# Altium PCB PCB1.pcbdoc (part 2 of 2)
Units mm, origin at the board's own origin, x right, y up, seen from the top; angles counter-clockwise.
Board outline 181.85 x 97.7 mm, 4 copper layers (Top Layer, GND, VCC, Bottom Layer); 121 components, 105 nets, 379 pads, 511 vias.
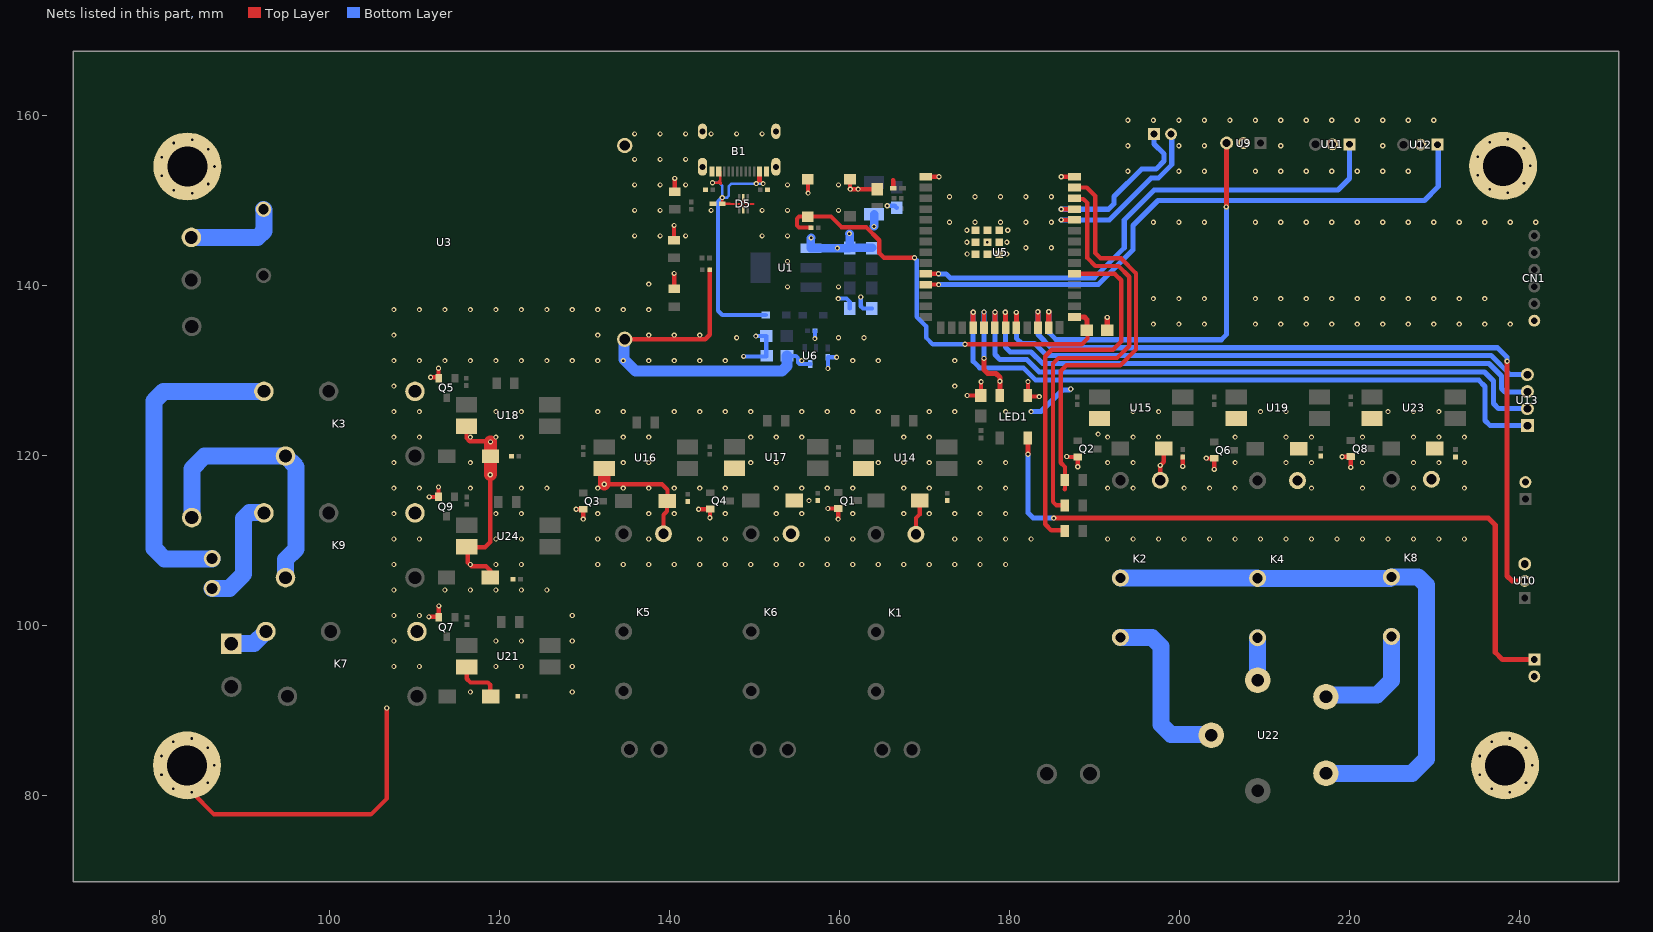
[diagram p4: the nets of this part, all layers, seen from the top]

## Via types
v1: diameter 0.61, hole 0.304, Top Layer to Bottom Layer, 331 vias
v2: diameter 0.61, hole 0.305, Top Layer to Bottom Layer, 168 vias
v3: diameter 0.5, hole 0.3, Top Layer to Bottom Layer, 12 vias

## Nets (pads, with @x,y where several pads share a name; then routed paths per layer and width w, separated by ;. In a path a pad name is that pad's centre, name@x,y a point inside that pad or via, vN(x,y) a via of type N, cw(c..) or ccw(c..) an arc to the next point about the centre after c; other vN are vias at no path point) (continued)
EXT_5V: C7.1 D1.1 D3.1 D7.1 D8.1 D9.1 D10.1 D11.1 D12.1 D13.1 K1.4 K2.4 K3.1 K4.4 K5.4 K6.4 K7.1 K8.4 K9.1 R5.1 R11.2 R12.2 R13.2 R14.2 R19.2 R20.2 R23.2 R24.2 R27.2 U3.4 U6.3 U14.4 U15.4 U16.4 U17.4 U18.4 U19.4 U21.4 U23.4 U24.4 | length 105.8
  Top Layer w0.5: U18.4@116.104,123.454 116.104,122.064 116.484,121.683 119.253,121.683 119.278,121.658 ; U21.4@116.143,95.099 116.143,93.729 116.586,93.286 118.618,93.286 118.897,93.007 118.897,91.72 D11.1@118.967,91.65 ; U24.4@116.143,109.257 U24.4@116.188,109.212 ; D13.1@118.889,105.652 118.889,106.503 118.415,106.977 116.688,106.977 116.256,107.409 116.256,109.144 U24.4@116.188,109.212 ; v2(118.898,117.742) 118.898,109.822 118.288,109.212 U24.4@116.188,109.212 ; v2(132.328,116.626) 139.119,116.626 139.776,115.968 139.776,114.722 D7.1@139.716,114.661 139.716,113.444 139.295,113.024 K5.4@139.295,110.788 ; U3.4@134.726,133.682 144.206,133.682 144.73,134.207 R5.1@144.73,141.876 ; K1.4@169.004,110.734 169.004,112.633 169.443,113.073 169.443,114.692 D1.1@169.435,114.7 ; K2.4@197.769,117.086 197.769,118.834 v2(197.764,118.839) 198.179,119.253 D3.1@198.179,120.823 ; v2(200.411,118.717) R12.2@200.411,119.845
  Top Layer w1.5: v2(118.898,117.742) 118.928,117.773 D9.1@118.928,119.926 v2(118.928,121.608) ; v2(132.328,116.626) U16.4@132.328,118.461
  Bottom Layer w0.5: C7.1@153.842,131.719 154.858,131.719 155.116,131.462 155.116,130.962 155.316,130.762 156.584,130.762 U6.3@156.592,130.769
  Bottom Layer w0.6: v1(182.564,125.171) 183.726,125.171 186.258,127.703 187.096,127.703 v2(187.223,127.83)
  Bottom Layer w1.3: U3.4@134.726,133.682 134.666,133.622 134.666,131.312 136.016,129.962 153.266,129.962 153.842,130.538 C7.1@153.842,131.719
  other v1: 116.564,92.171 128.564,92.171 107.564,95.171 110.564,95.171 119.564,95.171 122.564,95.171 128.564,95.171 107.564,98.171 119.564,98.171 122.564,98.171 128.564,98.171 107.564,101.171 110.564,101.171 128.564,101.171 107.564,104.171 113.564,104.171 116.564,104.171 119.564,104.171 122.564,104.171 125.564,104.171 107.564,107.171 116.564,107.171 119.564,107.171 122.564,107.171 131.564,107.171 134.564,107.171 137.564,107.171 140.564,107.171 143.564,107.171 146.564,107.171 149.564,107.171 152.564,107.171 155.564,107.171 158.564,107.171 161.564,107.171 164.564,107.171 167.564,107.171 170.564,107.171 173.564,107.171 176.564,107.171 179.564,107.171 107.564,110.171 110.564,110.171 119.564,110.171 122.564,110.171 131.564,110.171 137.564,110.171 143.564,110.171 146.564,110.171 152.564,110.171 158.564,110.171 161.564,110.171 173.564,110.171 176.564,110.171 179.564,110.171 182.564,110.171 191.564,110.171 194.564,110.171 197.564,110.171 200.564,110.171 203.564,110.171 206.564,110.171 209.564,110.171 212.564,110.171 215.564,110.171 218.564,110.171 221.564,110.171 224.564,110.171 227.564,110.171 230.564,110.171 233.564,110.171 107.564,113.171 119.564,113.171 122.564,113.171 131.564,113.171 137.564,113.171 140.564,113.171 146.564,113.171 152.564,113.171 155.564,113.171 161.564,113.171 167.564,113.171 170.564,113.171 173.564,113.171 176.564,113.171 179.564,113.171 107.564,116.171 110.564,116.171 116.564,116.171 122.564,116.171 125.564,116.171 131.564,116.171 134.564,116.171 137.564,116.171 140.564,116.171 143.564,116.171 146.564,116.171 152.564,116.171 155.564,116.171 158.564,116.171 161.564,116.171 167.564,116.171 170.564,116.171 176.564,116.171 179.564,116.171 191.564,116.171 194.564,116.171 200.564,116.171 203.564,116.171 206.564,116.171 215.564,116.171 221.564,116.171 227.564,116.171 233.564,116.171 107.564,119.171 116.564,119.171 134.564,119.171 137.564,119.171 149.564,119.171 152.564,119.171 164.564,119.171 167.564,119.171 170.564,119.171 176.564,119.171 179.564,119.171 191.564,119.171 194.564,119.171 206.564,119.171 212.564,119.171 215.564,119.171 221.564,119.171 227.564,119.171 230.564,119.171 233.564,119.171 107.564,122.171 110.564,122.171 116.564,122.171 119.564,122.171 122.564,122.171 134.564,122.171 137.564,122.171 149.564,122.171 152.564,122.171 155.564,122.171 167.564,122.171 170.564,122.171 191.564,122.171 194.564,122.171 197.564,122.171 206.564,122.171 212.564,122.171 215.564,122.171 221.564,122.171 227.564,122.171 230.564,122.171 233.564,122.171 107.564,125.171 110.564,125.171 119.564,125.171 122.564,125.171 131.564,125.171 134.564,125.171 140.564,125.171 143.564,125.171 146.564,125.171 149.564,125.171 155.564,125.171 158.564,125.171 161.564,125.171 164.564,125.171 170.564,125.171 173.564,125.171 179.564,125.171 194.564,125.171 197.564,125.171 209.564,125.171 212.564,125.171 224.564,125.171 227.564,125.171 230.564,125.171 107.564,128.171 173.564,128.171 107.564,131.171 110.564,131.171 113.564,131.171 116.564,131.171 119.564,131.171 122.564,131.171 125.564,131.171 128.564,131.171 131.564,131.171 134.564,131.171 137.564,131.171 140.564,131.171 143.564,131.171 146.564,131.171 155.564,131.171 161.564,131.171 164.564,131.171 173.564,131.171 107.564,134.171 131.564,134.171 137.564,134.171 140.564,134.171 143.564,134.171 107.564,137.171 110.564,137.171 113.564,137.171 116.564,137.171 119.564,137.171 122.564,137.171 125.564,137.171 128.564,137.171 131.564,137.171 134.564,137.171 137.564,137.171 137.564,140.171
  other v2: 156.417,114.7 190.449,122.522
FAN_SW: U5.18 U13.1 | length 78.3
  Top Layer w0.6: v2(175.743,136.873) 175.743,135.029 U5.18@175.746,135.026
  Bottom Layer w0.6: v2(175.743,136.873) 175.743,131.097 176.52,130.319 181.651,130.319 183.098,128.872 235.255,128.872 235.991,128.135 235.991,124.118 236.591,123.518 U13.1@240.973,123.518
FIN: K2.2 K4.2 K8.2 U22.P | length 69.5
  Bottom Layer w2: K2.2@193.069,105.586 209.176,105.586 K4.2@209.215,105.547 224.816,105.547 K8.2@224.972,105.703 224.999,105.73 228.102,105.73 229.077,104.755 229.077,84.279 227.4,82.602 U22.P@217.259,82.602
FO1: K2.3 U22.2 | length 20.9
  Bottom Layer w2: K2.3@193.069,98.586 196.79,98.586 197.837,97.539 197.837,88.335 199.007,87.165 203.687,87.165 U22.2@203.772,87.08
FO2: K4.3 U22.3 | length 5
  Bottom Layer w2: K4.3@209.215,98.547 209.215,93.575 U22.3@209.233,93.557
FO3: K8.3 U22.4 | length 13.7
  Bottom Layer w2: U22.4@217.259,91.602 217.464,91.806 223.266,91.806 224.972,93.512 K8.3@224.972,98.703
FSR1: LED5.2 U5.39 | length 48.4
  Top Layer w0.5: 186.529,116.043 186.553,116.066 186.553,118.645 186.053,119.145 186.053,129.962 186.715,130.624 193.065,130.624 194.92,132.478 194.92,141.445 193.142,143.223 190.729,143.223 190.119,143.832 190.119,150.538 189.111,151.546 U5.39@187.671,151.546
FSR2: LED7.2 U5.38 | length 49.9
  Top Layer w0.5: LED7.2@186.529,114.135 185.552,114.135 185.141,114.546 185.141,130.827 185.801,131.488 192.684,131.488 194.107,132.91 194.107,141.038 192.837,142.308 190.119,142.308 189.179,143.248 189.179,149.725 188.697,150.208 187.739,150.208 U5.38@187.671,150.276
FSR3: LED9.2 U5.31 | length 45.1
  Top Layer w0.5: LED9.2@186.529,111.135 186.471,111.193 184.937,111.193 184.222,111.908 184.222,131.687 184.988,132.453 192.202,132.453 193.167,133.418 193.167,140.632 192.413,141.386 U5.31@187.671,141.386
GND: B1.1 B1.A1 B1.A12 B1.B1 B1.B12 C1.2 C2.2 C3.2 C4.2 C5.2 C6.2 C7.2 C8.2 C9.2 C10.2 C11.2 C12.2 C13.2 C14.2 CN1.6 D5.2 LED1.3 LED11.2 LED12.2 LED13.2 pad.42 Q1.2 Q2.2 Q3.2 Q4.2 Q5.2 Q6.2 Q7.2 Q8.2 Q9.2 R8.1 R9.1 R10.2 SW1.2 SW2.2 U1.1 U3.3 U4.2 U5.1 U5.40 U5.41 U7.2 U9.2 U10.3 U11.2 U12.2 | length 108
  Top Layer w0.2: D5.2@148.692,150.348 148.692,149.836 148.916,149.612 149.916,149.612
  Top Layer w0.5: v2(83.766,80.386) 86.386,77.767 104.851,77.767 106.731,79.646 v2(106.731,90.289) ; v2(111.682,101.011) 112.779,101.011 Q7.2@112.838,100.952 112.852,100.966 v2(112.852,102.298) ; v2(111.721,115.129) 112.78,115.129 Q9.2@112.799,115.148 112.813,115.162 v2(112.813,116.299) ; v2(111.877,129.209) 112.74,129.209 Q5.2@112.813,129.136 ; v2(112.813,130.262) Q5.2@112.813,129.136 ; Q5.2@112.838,129.111 Q5.2@112.813,129.136 ; v2(129.007,113.682) 129.828,113.682 Q3.2@129.838,113.672 129.857,113.653 v2(129.857,112.516) ; v2(140.538,147.083) 140.543,147.078 LED11.2@140.543,145.353 ; v2(140.543,141.437) 140.557,141.423 LED12.2@140.557,139.616 ; v2(140.614,152.621) 140.621,152.614 LED13.2@140.621,151.068 ; v2(143.43,113.686) 144.751,113.686 Q4.2@144.776,113.711 144.776,112.692 v2(144.756,112.672) ; SW2.2@156.286,152.494 156.312,152.469 v2(156.312,150.893) ; v2(158.64,113.764) 159.855,113.764 Q1.2@159.869,113.75 159.849,113.73 v2(159.849,112.516) ; SW1.2@161.246,152.511 161.246,151.381 v2(161.265,151.362) 161.275,151.353 v2(162.196,151.353) C6.2@164.452,151.353 ; 166.319,152.417 166.333,152.404 C11.2@166.333,151.478 ; U5.1@170.171,152.816 171.712,152.816 v2(171.716,152.812) ; v2(175.021,127.064) 176.65,127.064 C5.2@176.659,127.055 176.67,127.066 v2(176.67,128.685) ; LED1.3@182.196,127.064 182.318,126.941 v2(183.515,126.941) ; LED1.3@182.197,127.065 v2(182.197,128.702) ; v2(186.116,152.812) 187.668,152.812 U5.40@187.671,152.816 ; v2(186.76,119.887) 186.813,119.834 Q2.2@188.028,119.834 188.047,119.815 v2(188.047,118.678) ; v2(203.18,119.692) 203.213,119.659 Q6.2@204.116,119.659 ; Q6.2@204.097,119.678 Q6.2@204.116,119.659 ; v2(204.116,118.366) Q6.2@204.116,119.659 ; v2(219.171,119.848) 220.18,119.848 Q8.2@220.185,119.853 ; v2(220.185,118.6) Q8.2@220.185,119.853 ; Q8.2@220.205,119.873 Q8.2@220.185,119.853
  Top Layer w0.6: C10.2@191.522,134.764 v2(191.522,136.263)
  Bottom Layer w0.5: v2(148.716,131.662) 151.384,131.662 C7.2@151.389,131.666 ; v2(150.166,134.062) 151.384,134.062 C12.2@151.392,134.069 C7.2@151.392,131.769 ; v2(157.116,133.762) 157.125,133.771 R8.1@157.125,134.669 ; v2(158.642,130.245) C13.2@158.642,131.574 159.653,131.574 v2(159.665,131.562) ; v2(159.868,138.473) 160.833,138.473 161.229,138.076 C2.2@161.229,137.311 ; v2(162.515,138.662) 162.515,137.577 162.785,137.308 163.826,137.308 C1.2@163.829,137.311 ; v2(165.633,149.395) 166.504,149.395 C9.2@166.737,149.162
  Bottom Layer w1: v2(156.666,145.612) 156.649,145.596 U1.1@156.649,144.411 v2(159.765,144.412) ; v2(159.765,144.412) C4.2@161.166,144.412 ; C4.2@161.166,144.462 161.19,144.486 161.19,146.116 v2(161.179,146.127) ; C4.2@161.19,144.436 C3.2@163.84,144.436 ; v2(164.065,146.962) 164.087,146.983 C8.2@164.087,148.401
  other v1: 147.893,133.853 159.893,133.853 162.893,133.853 196.954,135.464 199.954,135.464 202.954,135.464 208.954,135.464 211.954,135.464 214.954,135.464 217.954,135.464 220.954,135.464 223.954,135.464 226.954,135.464 229.954,135.464 232.954,135.464 235.954,135.464 238.954,135.464 196.954,138.464 199.954,138.464 202.954,138.464 208.954,138.464 211.954,138.464 214.954,138.464 217.954,138.464 220.954,138.464 223.954,138.464 226.954,138.464 229.954,138.464 232.954,138.464 235.954,138.464 153.893,139.853 159.893,139.853 153.893,142.853 181.954,144.464 184.954,144.464 135.893,145.853 138.893,145.853 141.893,145.853 150.893,145.853 153.893,145.853 172.954,147.464 175.954,147.464 178.954,147.464 181.954,147.464 184.954,147.464 196.954,147.464 199.954,147.464 202.954,147.464 208.954,147.464 211.954,147.464 214.954,147.464 217.954,147.464 220.954,147.464 223.954,147.464 226.954,147.464 229.954,147.464 232.954,147.464 235.954,147.464 238.954,147.464 241.954,147.464 135.893,148.853 138.893,148.853 144.893,148.853 150.893,148.853 153.893,148.853 159.893,148.853 172.954,150.464 175.954,150.464 178.954,150.464 181.954,150.464 184.954,150.464 135.893,151.853 138.893,151.853 141.893,151.853 153.893,151.853 159.893,151.853 193.954,153.464 199.954,153.464 202.954,153.464 208.954,153.464 211.954,153.464 214.954,153.464 217.954,153.464 220.954,153.464 223.954,153.464 226.954,153.464 135.893,154.853 138.893,154.853 141.893,154.853 193.954,156.464 199.954,156.464 202.954,156.464 211.954,156.464 223.954,156.464 135.893,157.853 138.893,157.853 141.893,157.853 144.893,157.853 147.893,157.853 150.893,157.853 193.954,159.464 196.954,159.464 199.954,159.464 202.954,159.464 205.954,159.464 208.954,159.464 211.954,159.464 214.954,159.464 217.954,159.464 220.954,159.464 223.954,159.464 226.954,159.464 229.954,159.464
  other v2: 238.915,80.386 81.611,80.767 236.759,80.767 85.662,81.481 240.81,81.481 80.204,82.443 80.204,82.443 235.352,82.443 235.352,82.443 86.411,83.538 86.411,83.538 241.559,83.538 241.559,83.538 80.204,84.632 235.352,84.632 85.662,85.595 240.81,85.595 81.611,86.309 236.759,86.309 83.766,86.689 238.915,86.689 175.021,143.717 179.716,143.712 174.998,145.095 177.421,145.095 179.716,145.112 174.998,146.521 179.818,146.525 83.805,150.862 238.681,150.94 81.65,151.242 236.525,151.32 85.701,151.957 240.576,152.035 80.243,152.919 80.243,152.919 235.118,152.997 235.118,152.997 86.45,154.014 86.45,154.014 241.325,154.092 241.325,154.092 80.243,155.108 235.118,155.186 85.701,156.071 240.576,156.149 81.65,156.785 236.525,156.863 83.805,157.165 238.681,157.243
IO0: C10.1 R4.1 SW2.1 U5.27 | length 52.8
  Top Layer w0.5: SW2.1@156.286,148.124 159.004,148.124 160.249,146.88 163.147,146.88 164.694,145.333 164.694,143.832 165.252,143.273 v2(168.834,143.273) ; SW2.1@156.286,148.124 155.246,148.125 154.998,147.877 154.998,147.06 155.229,146.829 R4.1@156.641,146.829 ; v2(174.777,133.088) 188.519,133.088 189.205,133.774 189.205,134.682 C10.1@189.122,134.764
  Top Layer w0.6: U5.27@187.671,136.306 188.832,136.306 189.154,135.984 189.154,134.796 C10.1@189.122,134.764
  Bottom Layer w0.5: v2(168.834,143.273) 169.088,143.019 169.088,136.339 170.205,135.222 170.205,133.875 170.993,133.088 v2(174.777,133.088)
IR_RX: U5.11 U12.1 | length 71.7
  Top Layer w0.5: U5.11@170.171,140.116 v2(171.679,140.116)
  Bottom Layer w0.6: v2(171.679,140.116) 190.465,140.116 194.564,144.214 194.564,147.083 197.506,150.025 228.849,150.025 230.48,151.655 230.48,156.508 U12.1@230.4,156.588
IR_TX: U5.10 U11.1 | length 60.8
  Top Layer w0.5: U5.10@170.171,141.386 v2(171.661,141.386)
  Bottom Layer w0.6: v2(171.661,141.386) 172.55,141.386 173.025,140.911 189.992,140.911 193.523,144.442 193.523,147.718 197.053,151.249 218.669,151.249 220.026,152.606 U11.1@220.026,156.627
N: U2.2 U3.1 | length 11.5
  Bottom Layer w2: U2.2@83.718,145.671 91.522,145.671 92.298,146.447 92.298,148.91 U3.1@92.226,148.983
NO1: CN6.1 K3.3 | length 38.1
  Bottom Layer w2: CN6.1@86.175,107.87 86.141,107.836 80.559,107.836 79.35,109.045 79.35,126.44 80.469,127.559 K3.3@92.262,127.559
NO2: CN6.2 K9.3 | length 13.6
  Bottom Layer w2: CN6.2@86.175,104.37 88.208,104.37 89.866,106.027 89.866,112.594 90.556,113.284 K9.3@92.223,113.284
NO3: CN5.1 K7.3 | length 4.6
  Bottom Layer w2: CN5.1@88.437,97.856 91.07,97.856 K7.3@92.496,99.282
P: K3.4 K9.4 U25.2 | length 32.7
  Bottom Layer w2: U25.2@83.772,112.694 83.772,118.409 85.289,119.926 94.79,119.926 K3.4@94.802,119.939 96.063,118.678 96.063,109.009 94.802,107.748 K9.4@94.802,105.625
PIR: U5.24 U10.2 | length 89
  Top Layer w0.6: v2(183.363,136.923) 183.363,135.029 U5.24@183.366,135.026 ; v2(238.582,131.107) 238.582,105.834 239.179,105.237 U10.2@240.661,105.237
  Bottom Layer w0.6: v2(183.363,136.923) 183.363,134.231 184.912,132.682 237.465,132.682 238.582,131.564 v2(238.582,131.107)
RGB: LED1.4 U5.19 | length 13.1
  Top Layer w0.5: v2(177.013,136.898) 177.016,136.894 U5.19@177.016,135.026
  Top Layer w0.6: v2(177.013,131.437) 177.013,130.091 177.444,129.659 178.435,129.659 178.892,129.202 v2(178.892,128.745) 178.894,128.743 LED1.4@178.894,127.062
  Bottom Layer w0.6: v2(177.013,131.437) v2(177.013,136.898)
RGB_O: LED1.2 U7.1 | length 84.3
  Top Layer w0.6: v2(182.194,120.159) LED1.2@182.194,122.062 ; v2(185.217,112.641) 236.372,112.641 237.185,111.828 237.185,96.842 238.023,96.004 U7.1@241.792,96.004
  Bottom Layer w0.6: v2(182.194,120.159) 182.194,113.251 182.804,112.641 v2(185.217,112.641)
RS2: U5.20 U13.2 | length 73.7
  Top Layer w0.6: U5.20@178.286,135.026 178.308,135.047 v2(178.308,136.873)
  Bottom Layer w0.6: v2(178.308,136.873) 178.308,131.885 178.908,131.285 182.067,131.285 183.515,129.837 235.925,129.837 236.982,128.78 236.982,126.118 237.582,125.518 U13.2@240.973,125.518
RS3: U5.21 U13.3 | length 70.5
  Top Layer w0.6: v2(179.527,136.873) 179.527,135.055 U5.21@179.556,135.026
  Bottom Layer w0.6: v2(179.527,136.873) 179.527,132.783 180.111,132.199 182.55,132.199 183.921,130.827 236.449,130.827 237.922,129.354 237.922,127.881 238.328,127.475 240.93,127.475 U13.3@240.973,127.518
RS4: U5.22 U13.4 | length 66.8
  Top Layer w0.6: v2(180.823,136.847) 180.823,135.029 U5.22@180.826,135.026
  Bottom Layer w0.6: v2(180.823,136.847) 180.823,133.79 181.423,133.19 182.982,133.19 184.404,131.767 236.705,131.767 238.955,129.518 U13.4@240.973,129.518
RXD0: U5.36 U8.2 | length 20.9
  Top Layer w0.5: v2(186.106,147.736) U5.36@187.671,147.736
  Bottom Layer w0.6: v2(186.106,147.736) 191.762,147.736 196.672,152.646 197.521,152.646 199.111,154.236 199.111,157.757 U8.2@199.032,157.836
TMP: U5.25 U9.3 | length 48.4
  Top Layer w0.6: v2(184.633,136.923) 184.633,135.029 U5.25@184.636,135.026 ; v2(205.537,149.268) 205.573,149.304 U9.3@205.573,156.783
  Bottom Layer w0.6: v2(184.633,136.923) 184.633,134.51 185.522,133.621 204.937,133.621 205.537,134.221 v2(205.537,149.268)
TXD0: U5.37 U8.1 | length 20.2
  Top Layer w0.5: v2(186.106,148.988) 187.654,148.988 U5.37@187.671,149.006
  Bottom Layer w0.6: v2(186.106,148.988) 191.683,148.988 192.329,149.634 192.329,150.482 195.585,153.738 197.282,153.738 198.204,154.66 198.204,155.509 197.032,156.681 U8.1@197.032,157.836
VBUS: B1.A4 B1.A9 B1.B4 B1.B9 C14.1 D2.1 D5.5 | length 37.8
  Top Layer w0.2: 147.066,149.612 148.456,149.612 148.692,149.376 D5.5@148.692,148.899
  Top Layer w0.3: v2(145.066,152.112) 145.716,152.112 ; B1.A9@145.652,153.418 B1.B4@145.952,153.418 145.952,152.348 145.716,152.112 ; 146.05,152.012 146.05,152.112 145.716,152.112 ; v2(146.216,150.362) 146.216,149.617 C14.1@146.211,149.612 147.066,149.612 ; v2(150.216,152.012) 150.452,152.248 B1.B9@150.452,153.418 ; B1.A4@150.752,153.418 150.752,152.275 v2(151.016,152.012)
  Bottom Layer w0.3: v2(145.066,152.112) 145.816,152.112 146.216,151.712 v2(146.216,150.362) 146.766,150.362 146.966,150.562 146.966,151.662 147.316,152.012 v2(150.216,152.012) v2(151.016,152.012)
  Bottom Layer w0.5: v2(146.216,150.362) 145.716,149.862 145.716,137.037 146.216,136.537 D2.1@151.342,136.537
pads on no net: B1.A8 B1.B8 K3.2 K7.2 K9.2 U5.16 U5.26 U5.28 U5.29 U5.30 U5.32 U5.33 U5.34 U5.35 U20.1 U20.2 U22.1
copper on no net:
  other v3: 176.721,143.695 178.121,143.695 176.021,144.395 177.421,144.395 178.821,144.395 176.721,145.095 178.121,145.095 176.021,145.795 177.421,145.795 178.821,145.795 176.721,146.495 178.121,146.495

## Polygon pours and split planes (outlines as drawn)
GND on Top Layer (solid, remove dead copper, pour order 8): 174.553,142.976 180.249,142.976 180.249,147.359 174.553,147.359
GND on Top Layer (solid, remove dead copper, pour order 0): 244.094,88.714 244.958,87.851 244.958,76.903 234.496,76.903 233.786,77.696 233.786,87.88 234.62,88.714
GND on Top Layer (solid, remove dead copper, pour order 2): 233.481,160.672 244.678,160.672 244.678,149.293 244.018,148.633 233.782,148.633 232.918,149.496 232.918,160.109
GND on Top Layer (solid, remove dead copper, pour order 4): 145.491,133.672 145.491,143.197 145.161,143.527 133.299,143.527 132.893,143.934 132.893,160.901 132.944,160.952 153.441,160.952 153.645,160.749 153.645,154.17 153.822,153.992 166.472,153.992 166.827,153.637 166.827,135.526 164.436,133.136 153.209,133.136 152.781,132.707 152.781,130.98 152.654,130.853 148.682,130.853 148.361,131.174 148.361,132.961 148.031,133.291 145.872,133.291
EXT_5V on Top Layer (solid, remove dead copper, pour order 6): 154.483,133.012 155.27,132.224 243.408,132.224 243.942,131.691 243.942,110.507 243.18,109.745 182.931,109.745 177.749,104.564 131.216,104.564 128.981,102.329 128.981,91.229 126.924,89.171 105.865,89.171 104.564,90.472 104.564,137.271 105.435,138.143 136.906,138.143 137.084,138.32 137.084,142.257 137.439,142.613 144.988,142.613 145.242,142.359 145.242,133.541 145.72,133.063 147.828,133.063 148.133,132.758 148.133,131.031 148.514,130.65 152.674,130.65 152.961,130.937 152.961,132.634 153.34,133.012
GND on Top Layer (solid, remove dead copper, pour order 10): 86.563,88.181 88.163,86.581 88.163,77.513 87.554,76.903 76.564,76.903 76.564,87.279 77.466,88.181
GND on Top Layer (solid, remove dead copper, pour order 12): 193.421,154.094 193.04,153.713 167.945,153.713 166.954,152.722 166.954,132.769 167.259,132.464 244.359,132.464 244.831,132.936 244.831,148.252 244.678,148.404 233.705,148.404 232.715,149.395 232.715,160.672 232.588,160.799 193.751,160.799 193.421,160.469
GND on GND (split plane): 244.864,160.853 245.09,76.782 233.463,76.782 233.239,108.029 ccw(c233.238,108.03) 233.238,108.031 232.107,109.162 ccw(c232.106,109.162) 232.106,109.163 183.235,109.163 ccw(c183.234,109.162) 183.233,109.162 177.568,103.497 131.37,103.497 ccw(c131.37,103.496) 131.368,103.496 129.899,102.026 ccw(c129.899,102.025) 129.898,102.025 129.898,90.668 127.529,88.299 105.39,88.299 103.736,89.953 103.736,138.23 120.4,138.23 ccw(c120.87,138.699) 121.339,139.169 ccw(c120.87,139.638) 120.4,140.108 103.736,140.108 103.736,146.23 121.043,146.23 ccw(c121.512,146.699) 121.982,147.169 ccw(c121.512,147.638) 121.043,148.108 103.736,148.108 103.736,154.23 121.101,154.23 ccw(c121.571,154.699) 122.04,155.169 ccw(c121.571,155.638) 121.101,156.108 103.736,156.108 103.736,160.114 ccw(c103.735,160.114) 103.735,160.115 103.634,160.217 ccw(c103.633,160.216) 103.632,160.218 88.736,160.218 ccw(c88.734,160.216) 88.733,160.215 88.733,148.984 88.489,148.74 76.852,148.74 ccw(c76.851,148.739) 76.85,148.739 76.457,148.346 76.457,160.777 153.652,160.948 153.573,154.288 ccw(c153.598,154.287) 153.573,154.287 ccw(c153.598,154.286) 153.573,154.285 ccw(c153.702,154.157) 153.83,154.029 193.045,154.068 ccw(c193.173,154.197) 193.302,154.325 ccw(c193.277,154.326) 193.302,154.327 ccw(c193.277,154.328) 193.302,154.329 193.188,160.853
GND on GND (split plane): 88.466,86.757 88.466,76.782 76.457,76.782 76.457,88.458 86.765,88.458
+5VCC on VCC (split plane): 244.864,160.853 245.09,76.782 233.463,76.782 233.239,108.029 ccw(c233.238,108.03) 233.238,108.031 232.107,109.162 ccw(c232.106,109.162) 232.106,109.163 183.235,109.163 ccw(c183.234,109.162) 183.233,109.162 177.568,103.497 131.37,103.497 ccw(c131.37,103.496) 131.368,103.496 129.899,102.026 ccw(c129.899,102.025) 129.898,102.025 129.898,90.668 127.529,88.299 105.39,88.299 103.736,89.953 103.736,138.23 120.4,138.23 ccw(c120.87,138.699) 121.339,139.169 ccw(c120.87,139.638) 120.4,140.108 103.736,140.108 103.736,146.23 121.043,146.23 ccw(c121.512,146.699) 121.982,147.169 ccw(c121.512,147.638) 121.043,148.108 103.736,148.108 103.736,154.23 121.101,154.23 ccw(c121.571,154.699) 122.04,155.169 ccw(c121.571,155.638) 121.101,156.108 103.736,156.108 103.736,160.114 ccw(c103.735,160.114) 103.735,160.115 103.634,160.217 ccw(c103.633,160.216) 103.632,160.218 88.736,160.218 ccw(c88.734,160.216) 88.733,160.215 88.733,148.984 88.489,148.74 76.852,148.74 ccw(c76.851,148.739) 76.85,148.739 76.457,148.346 76.457,160.777 153.652,160.948 153.573,154.288 ccw(c153.598,154.287) 153.573,154.287 ccw(c153.598,154.286) 153.573,154.285 ccw(c153.702,154.157) 153.83,154.029 193.045,154.068 ccw(c193.173,154.197) 193.302,154.325 ccw(c193.277,154.326) 193.302,154.327 ccw(c193.277,154.328) 193.302,154.329 193.188,160.853

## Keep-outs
Board Outline Layer:
  lines w0.254: 76.2,76.525 245.348,76.525 245.12,161.11 192.927,161.11 193.045,154.325 153.83,154.285 153.911,161.205 76.2,161.033 76.2,76.525
Multi-Layer:
  region: 102.458,155.851 121.101,155.851 cw(c121.101,155.169) 121.784,155.169 cw(c121.101,155.169) 121.101,154.486 102.458,154.486 cw(c102.458,155.169) 101.776,155.169 cw(c102.458,155.169)
  region: 102.4,147.851 121.043,147.851 cw(c121.043,147.169) 121.725,147.169 cw(c121.043,147.169) 121.043,146.486 102.4,146.486 cw(c102.4,147.169) 101.717,147.169 cw(c102.4,147.169)
  region: 101.757,139.851 120.4,139.851 cw(c120.4,139.169) 121.083,139.169 cw(c120.4,139.169) 120.4,138.486 101.757,138.486 cw(c101.757,139.169) 101.075,139.169 cw(c101.757,139.169)
  region: 109.108,143.851 127.751,143.851 cw(c127.751,143.169) 128.433,143.169 cw(c127.751,143.169) 127.751,142.486 109.108,142.486 cw(c109.108,143.169) 108.426,143.169 cw(c109.108,143.169)
  region: 109.108,151.851 127.751,151.851 cw(c127.751,151.169) 128.433,151.169 cw(c127.751,151.169) 127.751,150.486 109.108,150.486 cw(c109.108,151.169) 108.426,151.169 cw(c109.108,151.169)
  region: 108.874,135.43 127.517,135.43 cw(c127.517,134.747) 128.199,134.747 cw(c127.517,134.747) 127.517,134.064 108.874,134.064 cw(c108.874,134.747) 108.192,134.747 cw(c108.874,134.747)
  region: 191.721,108.334 199.308,108.334 cw(c199.308,107.846) 199.796,107.846 cw(c199.308,107.846) 199.308,107.358 191.721,107.358 cw(c191.721,107.846) 191.233,107.846 cw(c191.721,107.846)
  region: 207.86,108.303 215.447,108.303 cw(c215.447,107.815) 215.935,107.815 cw(c215.447,107.815) 215.447,107.327 207.86,107.327 cw(c207.86,107.815) 207.372,107.815 cw(c207.86,107.815)
  region: 223.616,108.269 231.204,108.269 cw(c231.204,107.781) 231.692,107.781 cw(c231.204,107.781) 231.204,107.293 223.616,107.293 cw(c223.616,107.781) 223.128,107.781 cw(c223.616,107.781)
  region: 141.249,96.182 142.418,96.182 142.418,99.636 139.598,102.456 132.359,102.456 132.359,101.292 138.882,101.292 141.249,98.925
  region: 156.306,96.151 157.475,96.151 157.475,99.606 154.655,102.425 147.416,102.425 147.416,101.261 153.939,101.261 156.306,98.894
  region: 170.891,96.042 172.06,96.042 172.06,99.497 169.24,102.316 162.001,102.316 162.001,101.152 168.524,101.152 170.891,98.785
  region: 97.726,111.549 97.726,110.431 101.319,110.431 102.756,112.174 102.756,119.093 101.592,119.093 101.592,112.608 100.719,111.549
  region: 97.841,125.811 97.841,124.693 101.434,124.693 102.87,126.436 102.87,133.355 101.706,133.355 101.706,126.871 100.833,125.811
  region: 97.892,97.541 97.892,96.423 101.485,96.423 102.921,98.166 102.921,105.085 101.757,105.085 101.757,98.6 100.884,97.541
  region: 91.164,130.365 93.529,130.365 95.193,128.701 95.193,125.399 93.005,123.211 82.795,123.211 82.078,122.494 82.078,111.294 82.608,110.765 87.494,110.765 88.392,109.866 88.392,106.775 87.331,105.714 81.694,105.714 81.656,105.752 81.656,106.349 87.046,106.349 87.788,107.091 87.788,109.484 87.237,110.035 82.02,110.035 81.182,110.873 81.182,123.149 82.316,124.284 92.631,124.284 94.144,125.797 94.144,128.432 93.15,129.426 91.164,129.426
  region: 91.453,115.463 93.198,115.463 94.526,114.135 94.526,111.332 93.195,110.001 93.195,104.907 94.111,103.991 95.66,103.991 96.481,104.812 96.481,106.43 97.121,106.43 97.121,104.563 95.909,103.351 93.885,103.351 92.501,104.735 92.501,110.213 93.942,111.654 93.942,113.888 92.962,114.868 91.453,114.868
  region: 91.858,101.387 93.921,101.373 94.936,100.275 94.936,98.242 92.044,95.35 87.65,95.3 86.739,94.389 86.739,91.528 87.255,90.969 89.288,90.969 89.288,90.407 87.012,90.407 86.205,91.28 86.205,94.701 87.436,95.932 91.727,95.932 94.358,98.562 94.358,99.921 93.604,100.738 91.858,100.738
  region: 76.378,88.46 76.378,148.264 76.852,148.738 88.49,148.738 88.736,148.983 88.736,160.215 103.632,160.215 103.734,160.114 103.734,89.952 105.389,88.296 127.53,88.296 129.9,90.667 129.9,102.025 131.37,103.494 177.569,103.494 183.235,109.16 232.106,109.16 233.237,108.029 233.461,76.751 88.468,76.751 88.468,86.758 86.766,88.46
  region: 133.226,91.282 133.226,92.922 133.996,93.692 135.246,93.692 136.069,92.868 136.069,90.078 136.726,89.422 136.726,84.201 137.605,83.321 139.845,83.321 140.946,84.422 140.946,86.832 140.236,86.832 140.236,84.752 139.456,83.972 138.046,83.972 137.376,84.642 137.376,89.802 136.716,90.462 136.716,93.192 135.566,94.342 133.746,94.342 132.596,93.192 132.596,91.282
  region: 148.211,91.277 148.211,92.917 148.981,93.687 150.231,93.687 151.054,92.863 151.054,90.073 151.921,89.207 151.921,84.236 152.8,83.357 155,83.357 156.101,84.457 156.101,86.827 155.371,86.827 155.371,84.767 154.571,83.967 153.181,83.967 152.551,84.597 152.551,89.607 151.701,90.457 151.701,93.187 150.551,94.337 148.731,94.337 147.581,93.187 147.581,91.277
  region: 162.905,91.242 162.905,92.882 163.675,93.652 164.925,93.652 165.749,92.828 165.749,90.038 166.505,89.282 166.505,84.221 167.455,83.272 169.775,83.272 170.795,84.292 170.795,86.792 170.065,86.792 170.065,84.622 169.425,83.982 167.735,83.982 167.155,84.562 167.155,89.662 166.395,90.422 166.395,93.152 165.245,94.302 163.425,94.302 162.275,93.152 162.275,91.242
  region: 81.856,139.802 81.856,140.515 83.836,143.112 92.636,143.112 94.816,145.292 94.816,150.232 94.006,151.042 90.716,151.042 89.886,150.212 89.886,148.192 90.546,148.192 90.546,148.93 92.286,150.482 94.006,148.882 94.006,145.652 92.266,143.912 82.596,143.912 80.986,142.302 80.986,139.802
  circle w0.254: c145.312,154.463 r0.325
  circle w0.254: c151.092,154.463 r0.325

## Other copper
Top Layer:
  region net GND: 76.556,160.698 76.556,149.877 77.14,149.293 87.274,149.293 88.214,150.233 88.214,160.393 87.909,160.698

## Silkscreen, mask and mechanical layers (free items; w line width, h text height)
Top Silkscreen Layer:
  lines w0.254: 91.858,101.387 91.858,101.394 91.866,101.402
  lines w0.3: 194.366,136.541 233.874,136.541 233.874,150.075 194.366,150.075 194.366,136.541
  lines w0.75: 173.032,106.452 176.776,106.393 181.066,110.683 ; 179.929,101.785 184.219,106.075 187.964,106.016 ; 171.199,106.51 172.41,107.721 173.032,107.721 173.032,105.184 172.525,105.184 171.199,106.51 ; 187.964,104.747 188.586,104.747 189.797,105.958 188.471,107.284 187.964,107.284 187.964,104.747
  lines w1: 129.935,76.947 129.935,102.025 131.405,103.494 133.484,103.494 177.544,103.494 183.184,109.135 227.962,109.135 ; 227.962,109.16 232.055,109.16 233.211,108.004 233.211,103.429 233.211,78.852 231.306,76.947
  text "AC IN" at 76.932,145.901 h2 r270
  text "SHA_PCB_V1.0_REV_0.0" at 195.859,145.255 h3.05
  text "SAI AUTOMATIONS" at 195.853,140.508 h4
  text "SALEM" at 210.02,137.854 h1.98
  text "LV" at 173.847,108.943 h2.83
  text "HV" at 183.46,101.708 h2.83
  text "⚡⚡" at 172.314,99.484 h2.5
  text "⚠WARNING /  " at 174.475,92.157 h2.5
Bottom Silkscreen Layer:
  lines w1: 76.971,78.936 78.648,77.259 228.531,77.259 231.62,77.259 233.211,78.852 233.211,105.145 233.211,108.029 232.08,109.16 183.21,109.16 177.544,103.494 131.405,103.494 129.935,102.025 129.875,90.667 127.53,88.271 105.364,88.296 103.726,89.934 103.726,160.215 88.71,160.215 88.71,149.997 87.451,148.738 78.325,148.738 76.971,147.384 76.971,78.936
  text "TXD0" at 198.092,156.675 h0.97 r90
  text "RXD0" at 200.409,156.658 h0.97 r90
  text "Temp" at 206.382,155.969 h0.97 r90
  text "Gnd" at 208.622,155.852 h0.97 r90
  text "+5vcc" at 217.047,155.664 h0.97 r90
  text "5v" at 210.806,155.653 h0.97 r90
  text "Tx" at 221.194,155.617 h0.97 r90
  text "Gnd" at 219.075,155.579 h0.97 r90
  text "5vcc" at 227.533,155.414 h0.97 r90
  text "Gnd" at 229.466,155.371 h0.97 r90
  text "Rx" at 231.533,155.328 h0.97 r90
  text "Sw1" at 240.088,145.747 h0.97
  text "N" at 82.041,145.043 h2
  text "Sw2" at 240.093,143.618 h0.97
  text "Sw3" at 240.099,141.411 h0.97
  text "LIVE" at 82.119,139.973 h2
  text "Sw4" at 240.104,139.519 h0.97
  text "Sw5" at 240.265,137.615 h0.97
  text "Gnd" at 240.304,135.47 h0.97
  text "Sp3" at 239.574,128.801 h0.97
  text "Sp2" at 239.368,126.812 h0.97
  text "Sp1" at 239.212,124.823 h0.97
  text "F_Sw" at 239.287,122.951 h0.97
  text "Gnd" at 239.161,116.429 h0.97
  text "+5v" at 239.161,114.353 h0.97
  text "Gnd" at 238.999,106.717 h0.97
  text "NO" at 84.732,106.315 h2
  text "Pir_Out" at 238.846,104.737 h0.97
  text "NO" at 84.693,103.039 h2
  text "+5v" at 238.926,102.81 h0.97
  text "NO" at 85.2,96.915 h2
  text "RGB_O" at 240.063,95.532 h0.97
  text "⚠WARNING" at 190.947,94.926 h3
  text "Gnd" at 240.091,93.417 h0.97
  text "COM" at 85.434,91.728 h2
  text "HIGH VOLTAGE /   110-240 VAC" at 192.546,88.062 h3
  text "⚡⚡⚡" at 185.799,85.566 h2
  text "COM" at 169.756,84.162 h2 r90
  text "NO" at 166.323,83.967 h2 r90
  text "COM" at 140.153,83.928 h2 r90
  text "NO" at 151.62,83.928 h2 r90
  text "COM" at 155.286,83.928 h2 r90
  text "NO" at 136.292,83.889 h2 r90
  text "⚠WARNING" at 120.904,83.582 h3
  text "HIGH VOLTAGE 110-240 VAC" at 129.367,80.189 h3
  text "⚡⚡⚡" at 115.717,78.2 h2
Mechanical Layer:
  drawing of 280 lines, arcs and shapes, not listed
